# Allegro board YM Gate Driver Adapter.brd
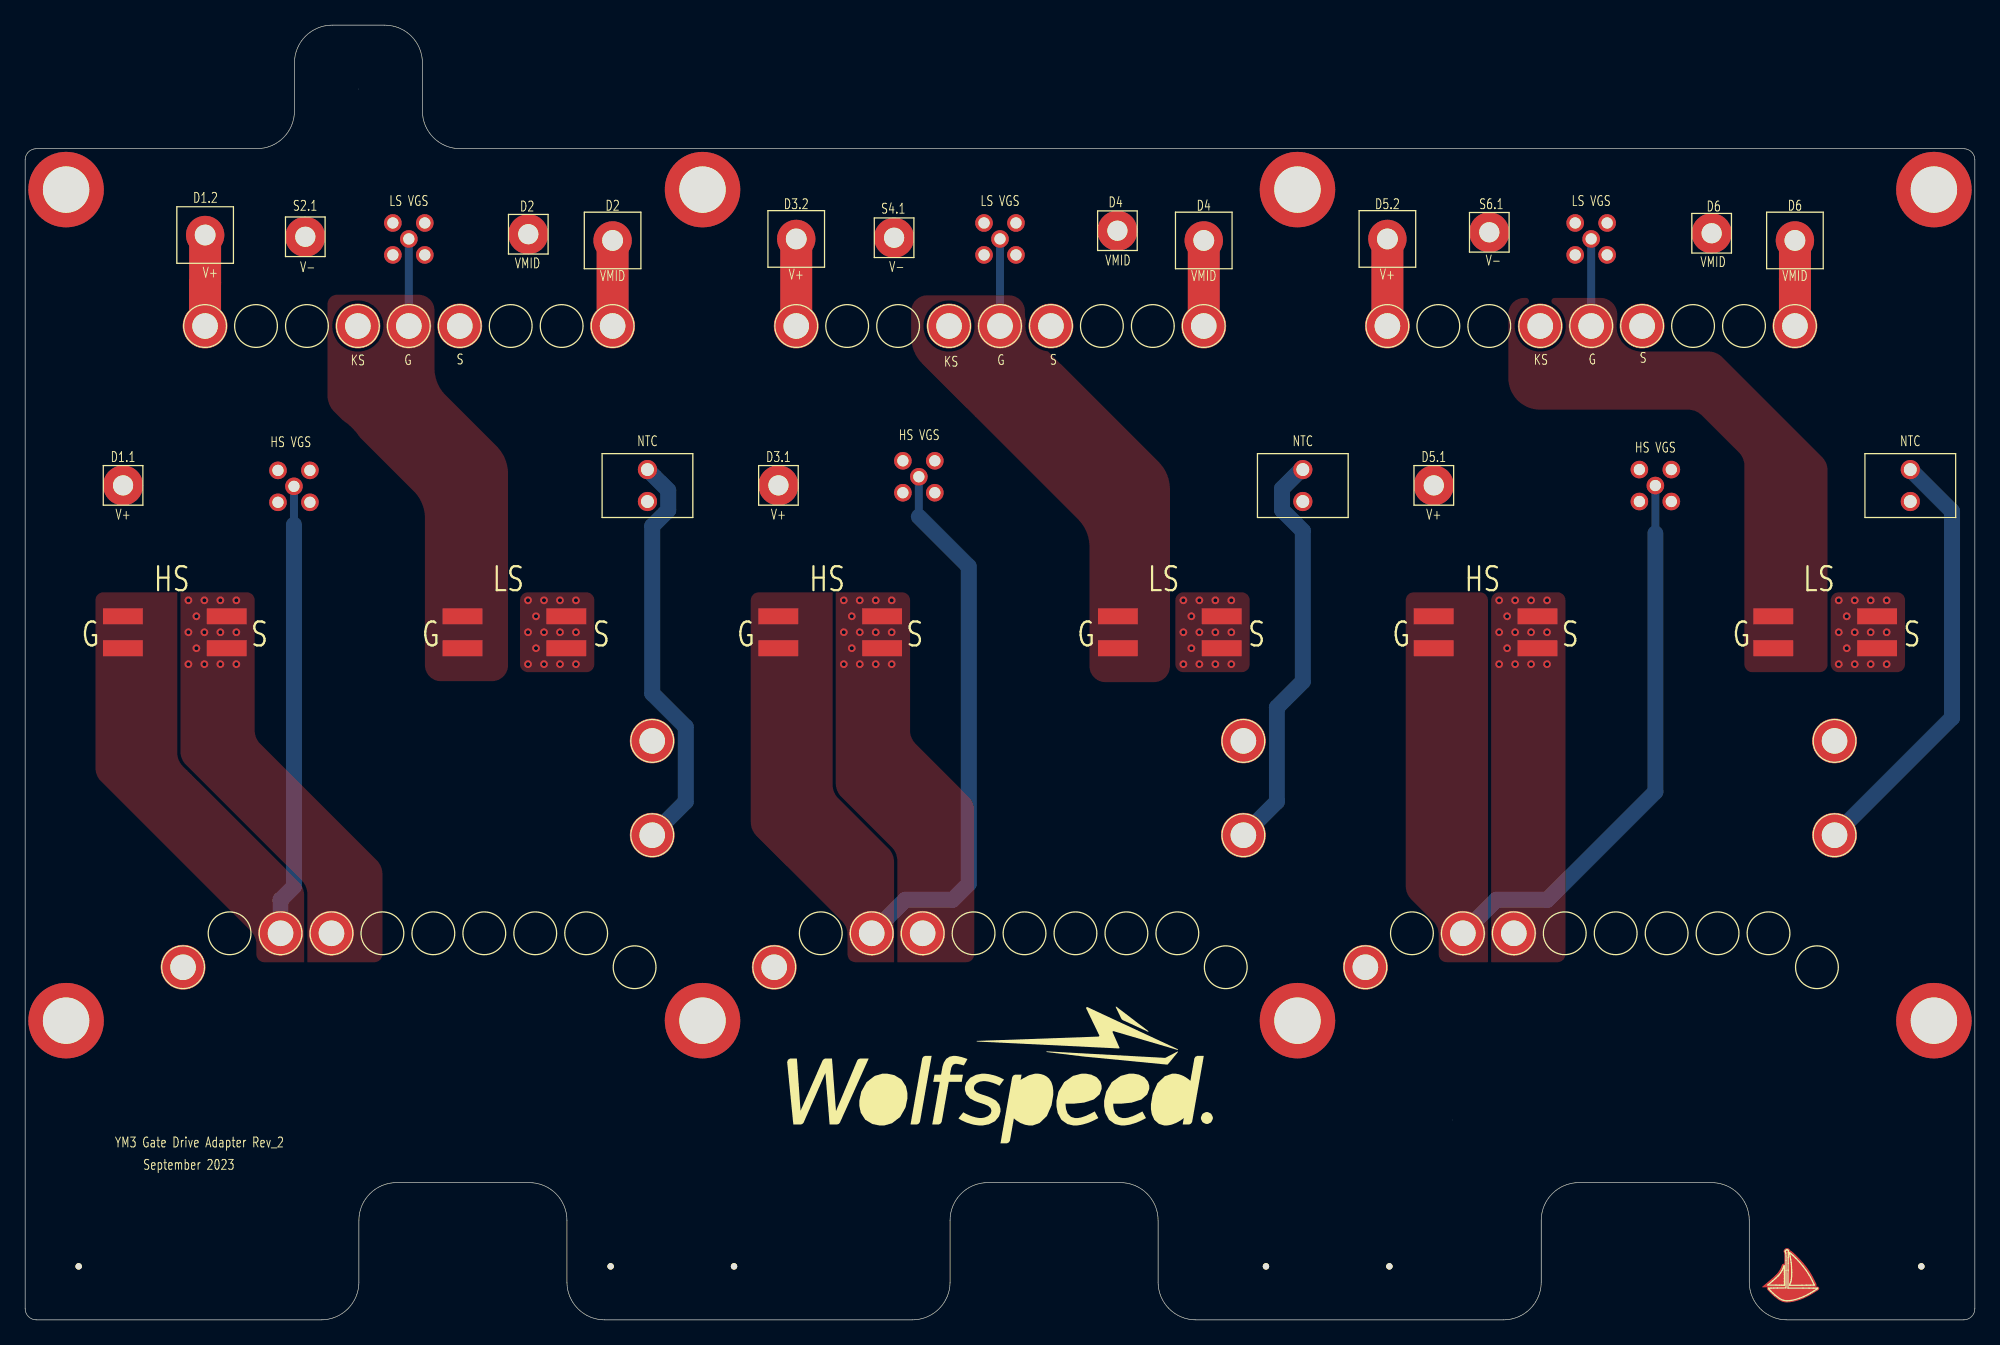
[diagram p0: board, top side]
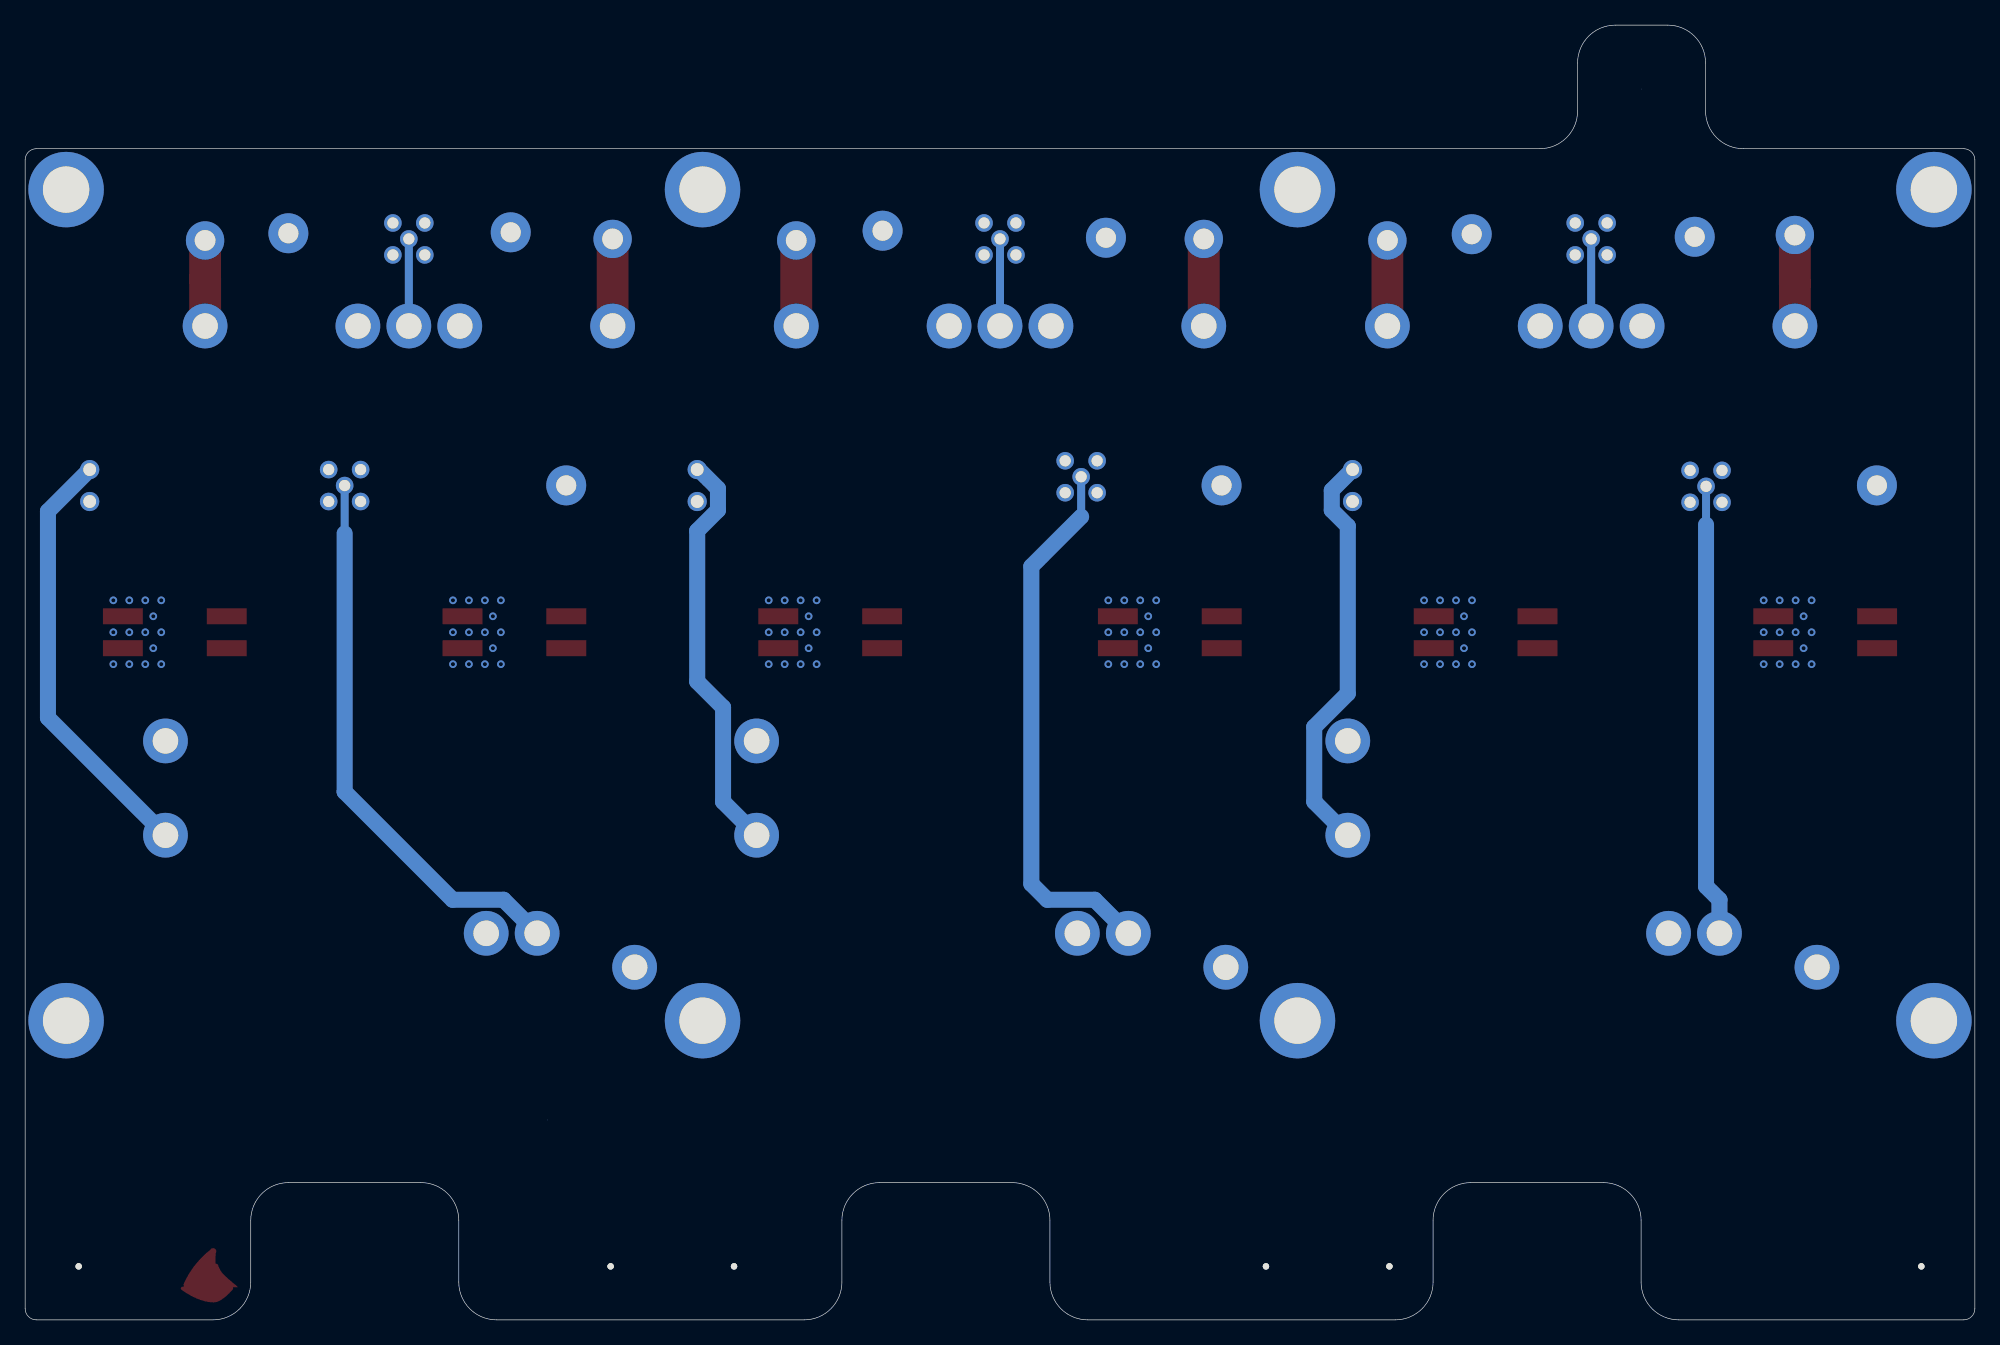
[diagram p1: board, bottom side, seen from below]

Outline 155.01 x 102.98 mm; copper layers: TOP, LAYER2, LAYER3, BOTTOM. Coordinates in mm from the lower left corner of the outline.
Outline path: 0,92.26 arc(0.26,92.89) 0.89,93.15 18.41,93.15 arc(20.53,94.03) 21.41,96.15 21.41,99.98 arc(22.29,102.1) 24.41,102.98 28.58,102.98 arc(30.71,102.1) 31.58,99.98 31.58,96.15 arc(32.46,94.03) 34.58,93.15 154.12,93.15 arc(154.75,92.89) 155.01,92.26 155.01,0.89 arc(154.75,0.26) 154.12,0 140.07,0 arc(137.95,0.88) 137.07,3 137.07,7.92 arc(136.2,10.04) 134.07,10.92 123.53,10.92 arc(121.41,10.04) 120.53,7.92 120.53,3 arc(119.66,0.88) 117.53,0 93.07,0 arc(90.95,0.88) 90.07,3 90.07,7.92 arc(89.2,10.04) 87.07,10.92 76.53,10.92 arc(74.41,10.04) 73.53,7.92 73.53,3 arc(72.66,0.88) 70.53,0 46.07,0 arc(43.95,0.88) 43.07,3 43.07,7.92 arc(42.2,10.04) 40.07,10.92 29.53,10.92 arc(27.41,10.04) 26.53,7.92 26.53,3 arc(25.66,0.88) 23.53,0 0.89,0 arc(0.26,0.26) 0,0.89 0,92.26

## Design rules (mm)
constraint set DEFAULT: min track width 0.254
net group NTC1: nets T1.1 T1.2
net group NTC2: nets T2.1 T2.2
net group NTC3: nets T3.1 T3.2
net group V+_1: nets D1.1 D1.2
net group V+_2: nets D3.1 D3.2
net group V+_3: nets D5.1 D5.2
net group V-_1: nets S2.2
net group V-_2: nets S4.2
net group V-_3: nets S6.2
net group VMID_1: nets D2
net group VMID_2: nets D4
net group VMID_3: nets D6

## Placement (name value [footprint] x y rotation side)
JT1  735187-2  [CON_1X1_63MIL]  14.31 86.28 0 top
JT2  TEST POINT  [CON1_TP]  22.27 86.14 0 top
JT3  DNP  [MMCX_PLUG_TH]  30.5 85.97 0 top
JT4  735187-2  [CON_1X1_63MIL]  61.3 85.97 0 top
JT5  TEST POINT  [CON1_TP]  69.08 86.07 0 top
JT6  DNP  [MMCX_PLUG_TH]  77.5 85.97 0 top
JT7  735187-2  [CON_1X1_63MIL]  108.3 85.97 0 top
JT8  TEST POINT  [CON1_TP]  116.4 86.5 0 top
JT9  DNP  [MMCX_PLUG_TH]  124.5 85.97 0 top
JT10  TEST POINT  [CON1_TP]  40 86.35 0 top
JT11  735187-2  [CON_1X1_63MIL]  46.7 85.85 0 top
JT12  TEST POINT  [CON1_TP]  86.84 86.63 0 top
JT13  735187-2  [CON_1X1_63MIL]  93.7 85.85 0 top
JT14  TEST POINT  [CON1_TP]  134.08 86.42 0 top
JT15  735187-2  [CON_1X1_63MIL]  140.7 85.85 0 top
JT16  TEST POINT  [CON1_TP]  7.79 66.37 0 top
JT17  DNP  [MMCX_PLUG_TH]  21.37 66.29 0 top
JT18  0022280020  [CONN_HEADER_2POS_LOCKING]  49.48 66.36 0 top
JT19  TEST POINT  [CON1_TP]  59.89 66.37 0 top
JT20  DNP  [MMCX_PLUG_TH]  71.05 67.06 0 top
JT21  0022280020  [CONN_HEADER_2POS_LOCKING]  101.58 66.36 0 top
JT22  TEST POINT  [CON1_TP]  111.99 66.37 0 top
JT23  DNP  [MMCX_PLUG_TH]  129.61 66.36 0 top
JT24  0022280020  [CONN_HEADER_2POS_LOCKING]  149.88 66.36 0 top
NOREF  -  []  77.5 19.48 0 top
NOREF#2  -  []  138.32 1.33 0 top
NOREF#3  -  []  0 46.57 0 top
NOREF#4  -  []  138.32 1.33 0 top
NOREF#5  -  []  58.3 0 90 top
UT1  HybridPack_DriverOnly  [HYBRIDPACK_DRIVERONLY]  26.5 97.9 0 top
UT2  XGD1700HB2P-FM3  [XGD1700HB2P-FM3_NOMIDDLEMOUNT]  25.4 29.84 180 top
UT3  XGD1700HB2P-FM3  [XGD1700HB2P-FM3_NOMIDDLEMOUNT]  77.5 29.84 180 top
UT4  XGD1700HB2P-FM3  [XGD1700HB2P-FM3_NOMIDDLEMOUNT]  129.61 29.84 180 top

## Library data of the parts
JT1 JT4 JT7 JT11 JT13 JT15 = HDR_1X1_M
JT2 JT5 JT8 JT10 JT12 JT14 JT16 JT19 JT22 = TEST POINT
JT3 JT6 JT9 JT17 JT20 JT23 = BNC_5P
JT18 JT21 JT24 = 0022280020
UT1 = HybridPack_DriverOnly_2
UT2-UT4 = XGD1700HB2P-FM3

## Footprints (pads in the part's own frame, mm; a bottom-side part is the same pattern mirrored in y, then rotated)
CON1_TP
  round 3.175 hole 1.6: 1(0,0)
CON_1X1_63MIL
  round 3.048 hole 1.651: 1(0,0)
CONN_HEADER_2POS_LOCKING
  round 1.524 hole 1.016: 1(0,1.27) 2(0,-1.27)
HYBRIDPACK_DRIVERONLY
  round 6 hole 3.683: (-23.25,-8) (-23.25,-74.1) (27.35,-74.1) (27.351,-8.001) (74.65,-8) (74.65,-74.1) (125.25,-8) (125.25,-74.1)
  round 0.025 hole 5.842 unplated: (0,0)
  round 0.025 hole 4.826 unplated: (87,-82)
  round 3.556 hole 2.032: 1(-12.2,-18.85) 2(-13.95,-69.85) 3(-6.2,-67.15) 4(-2.15,-67.15) 5(20.2,-18.85) 6(4,-18.85) 7(-0.05,-18.85) 8(8.05,-18.85) 9(34.8,-18.85) 10(33.05,-69.85) 11(40.8,-67.15) 12(44.85,-67.15) 13(67.2,-18.85) 14(51,-18.85) 15(46.95,-18.85) 16(55.05,-18.85) 17(81.8,-18.85) 18(80.05,-69.85) 19(87.8,-67.15) 20(91.85,-67.15) 21(114.2,-18.85) 22(98,-18.85) 23(93.95,-18.85) 24(102.05,-18.85) 25(23.35,-51.85) 26(23.35,-59.35) 27(70.35,-51.85) 28(70.35,-59.35) 29(117.35,-51.85) 30(117.35,-59.35)
MMCX_PLUG_TH
  round 1.397 hole 0.889: 1(0,0) 2(-1.27,1.27) 3(1.27,1.27) 4(1.27,-1.27) 5(-1.27,-1.27)
XGD1700HB2P-FM3_NOMIDDLEMOUNT
  round 0.508 hole 4.445 unplated: (-21.146,25.591) (21.146,25.591)
  rect 3.175x1.27 smd: 1(17.628,-26.115) 2(9.373,-26.115) 3(-9.373,-26.115) 4(-17.628,-26.115) 12(17.628,-23.575) 22(9.373,-23.575) 32(-9.373,-23.575) 42(-17.628,-23.575)

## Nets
D1.1: JT16.1 UT1.2
D1.2: JT1.1 UT1.1
D2: JT10.1 JT11.1 UT1.5
D3.1: JT19.1 UT1.10
D3.2: JT4.1 UT1.9
D4: JT12.1 JT13.1 UT1.13
D5.1: JT22.1 UT1.18
D5.2: JT7.1 UT1.17
D6: JT14.1 JT15.1 UT1.21
G1: JT17.1(SIGNAL) UT1.3 UT2.1 UT2.12
G2: JT3.1(SIGNAL) UT1.6 UT2.3 UT2.32
G3: JT20.1(SIGNAL) UT1.11 UT3.1 UT3.12
G4: JT6.1(SIGNAL) UT1.14 UT3.3 UT3.32
G5: JT23.1(SIGNAL) UT1.19 UT4.1 UT4.12
G6: JT9.1(SIGNAL) UT1.22 UT4.3 UT4.32
S1: JT17.2 JT17.3 JT17.4 JT17.5 UT1.4 UT2.2 UT2.22
S2.1: JT2.1 JT3.2 JT3.3 JT3.4 JT3.5 UT1.7 UT2.4 UT2.42(LS-SOURCE-2)
S2.2: UT1.8
S3: JT20.2 JT20.3 JT20.4 JT20.5 UT1.12 UT3.2 UT3.22
S4.1: JT5.1 JT6.2 JT6.3 JT6.4 JT6.5 UT1.15 UT3.4 UT3.42(LS-SOURCE-2)
S4.2: UT1.16
S5: JT23.2 JT23.3 JT23.4 JT23.5 UT1.20 UT4.2 UT4.22
S6.1: JT8.1 JT9.2 JT9.3 JT9.4 JT9.5 UT1.23 UT4.4 UT4.42(LS-SOURCE-2)
S6.2: UT1.24
T1.1: JT18.2 UT1.25
T1.2: JT18.1 UT1.26
T2.1: JT21.2 UT1.27
T2.2: JT21.1 UT1.28
T3.1: JT24.2 UT1.29
T3.2: JT24.1 UT1.30(T3.2)

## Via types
v1: diameter 0.61, hole 0.33, TOP to BOTTOM, 84 vias

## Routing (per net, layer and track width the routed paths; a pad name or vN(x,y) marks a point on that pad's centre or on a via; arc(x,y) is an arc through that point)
D1.1: length 45.5
  LAYER3 w1.27: UT1.2 1.56,39.04 1.56,60.14 JT16.1
D1.2: length 7.2
  TOP w0.635: 14.3,82.47 14.31,82.48
  TOP w2.54: UT1.1 14.3,82.47 ; 14.31,82.48 JT1.1
D2: length 16.9
  TOP w2.54: UT1.5 JT11.1
  LAYER2 w2.54: UT1.5 40,85.75 JT10.1
D3.1: length 41.9
  LAYER3 w1.27: UT1.10 55.41,32.19 55.41,61.89 JT19.1
D3.2: length 6.9
  TOP w2.54: UT1.9 JT4.1
D4: length 17.2
  TOP w2.54: UT1.13 JT13.1
  LAYER2 w2.54: JT12.1 86.84,85.91 UT1.13
D5.1: length 40.6
  LAYER3 w1.27: UT1.18 106.55,60.93 JT22.1
D5.2: length 6.9
  TOP w2.54: UT1.17 JT7.1
D6: length 16.9
  TOP w2.54: JT15.1 140.7,82.8 UT1.21
  LAYER2 w2.54: UT1.21 134.08,85.67 JT14.1
G1: length 36
  BOTTOM w0.635: JT17.1 21.37,63.25
  BOTTOM w1.27: 21.37,63.25 21.37,34.48 20.3,33.41 UT1.3
G2: length 6.9
  BOTTOM w0.635: JT3.1 UT1.6
G3: length 43.4
  BOTTOM w0.635: JT20.1 71.05,63.88
  BOTTOM w1.27: 71.05,63.88 75.01,59.92 75.01,34.68 73.74,33.41 69.97,33.41 UT1.11
G4: length 6.9
  BOTTOM w0.635: JT6.1 77.5,84.17 UT1.14
G5: length 44.3
  BOTTOM w0.635: 129.61,62.55 JT23.1
  BOTTOM w1.27: 129.61,62.55 129.61,42 121.02,33.41 116.97,33.41 UT1.19
G6: length 6.9
  BOTTOM w0.635: UT1.22 JT9.1
S1: length 33.2
  LAYER3 w2.54: 21.37,62.74 21.37,37.03 24.35,34.05 UT1.4
  vias: v1(12.98,57.23) v1(12.98,54.69) v1(12.98,52.15) v1(13.61,55.96) v1(13.61,53.42) v1(14.25,57.23) v1(14.25,54.69) v1(14.25,52.15) v1(15.52,57.23) v1(15.52,54.69) v1(15.52,52.15) v1(16.79,57.23) v1(16.79,54.69) v1(16.79,52.15)
S2.1: length 8.8
  LAYER2 w2.54: UT1.7 22.27,83.23 JT2.1
  vias: v1(39.98,57.23) v1(39.98,54.69) v1(39.98,52.15) v1(40.61,55.96) v1(40.61,53.42) v1(41.25,57.23) v1(41.25,54.69) v1(41.25,52.15) v1(42.52,57.23) v1(42.52,54.69) v1(42.52,52.15) v1(43.79,57.23) v1(43.79,54.69) v1(43.79,52.15)
S3: length 36.4
  LAYER3 w2.54: 71.05,63.91 75.07,59.9 75.07,34.46 UT1.12
  vias: v1(65.08,57.23) v1(65.08,54.69) v1(65.08,52.15) v1(65.72,55.96) v1(65.72,53.42) v1(66.35,57.23) v1(66.35,54.69) v1(66.35,52.15) v1(67.62,57.23) v1(67.62,54.69) v1(67.62,52.15) v1(68.89,57.23) v1(68.89,54.69) v1(68.89,52.15)
S4.1: length 8.8
  LAYER2 w2.54: JT5.1 69.08,83.42 UT1.15
  vias: v1(92.08,57.23) v1(92.08,54.69) v1(92.08,52.15) v1(92.72,55.96) v1(92.72,53.42) v1(93.35,57.23) v1(93.35,54.69) v1(93.35,52.15) v1(94.62,57.23) v1(94.62,54.69) v1(94.62,52.15) v1(95.89,57.23) v1(95.89,54.69) v1(95.89,52.15)
S5: length 36.5
  LAYER3 w2.54: UT1.20 129.61,42 129.61,62.55
  vias: v1(117.19,57.23) v1(117.19,54.69) v1(117.19,52.15) v1(117.82,55.96) v1(117.82,53.42) v1(118.46,57.23) v1(118.46,54.69) v1(118.46,52.15) v1(119.73,57.23) v1(119.73,54.69) v1(119.73,52.15) v1(121,57.23) v1(121,54.69) v1(121,52.15)
S6.1: length 9.1
  LAYER2 w2.54: JT8.1 116.4,83.1 UT1.23
  vias: v1(144.19,57.23) v1(144.19,54.69) v1(144.19,52.15) v1(144.82,55.96) v1(144.82,53.42) v1(145.46,57.23) v1(145.46,54.69) v1(145.46,52.15) v1(146.73,57.23) v1(146.73,54.69) v1(146.73,52.15) v1(148,57.23) v1(148,54.69) v1(148,52.15)
T1.1: length 19.2
  LAYER3 w1.27: UT1.25 49.85,64.71 JT18.2
T1.2: length 32.5
  BOTTOM w1.27: JT18.1 51.13,65.98 51.13,64.4 49.85,63.13 49.85,49.82 52.52,47.15 52.52,41.21 UT1.26
T2.1: length 21
  LAYER3 w1.27: JT21.2 101.58,50.77 UT1.27
T2.2: length 32.5
  BOTTOM w1.27: JT21.1 101.44,67.63 99.93,66.11 99.93,64.4 101.58,62.75 101.58,50.77 99.52,48.71 99.52,41.21 UT1.28
T3.1: length 28.7
  LAYER3 w1.27: UT1.29 151.35,46.05 153.2,47.89 153.2,61.77 JT24.2
T3.2: length 34.3
  BOTTOM w1.27: JT24.1 153.2,64.31 153.2,47.89 UT1.30

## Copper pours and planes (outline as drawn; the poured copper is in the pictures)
G1 on TOP: 22.18,28.45 22.18,33.75 22.07,34.34 21.73,34.84 12.54,44.03 12.21,44.53 12.09,45.12 12.09,57.87 6.22,57.87 5.77,57.68 5.59,57.23 5.59,43.91 5.7,43.32 6.04,42.83 17.93,30.93 18.27,30.43 18.38,29.84 18.38,29.08 18.57,28.63 19.02,28.45
G3 on TOP: 69.08,28.45 69.08,36.42 68.97,37 68.63,37.5 64.64,41.49 64.31,41.99 64.19,42.57 64.19,57.87 58.33,57.87 57.88,57.68 57.69,57.23 57.69,39.58 57.81,39 58.14,38.5 64.93,31.71 65.27,31.21 65.38,30.62 65.38,29.08 65.57,28.63 66.02,28.45
G4 on TOP: 70.44,80.21 70.81,81.11 71.71,81.48 78.22,81.48 79.11,81.11 79.49,80.21 79.49,80.13 79.72,78.96 80.38,77.96 90.12,68.23 90.78,67.24 91.01,66.06 91.01,51.99 90.64,51.1 89.74,50.72 85.89,50.72 84.99,51.1 84.62,51.99 84.62,61.49 84.38,62.67 83.72,63.66 71.34,76.04 70.68,77.03 70.44,78.21
G6 on TOP: 117.92,80.01 118.29,80.91 119.19,81.28 125.25,81.28 126.19,80.89 126.58,79.95 126.58,79.55 127.32,77.76 129.12,77.01 133.84,77.01 134.43,76.9 134.92,76.56 142.85,68.64 143.18,68.14 143.3,67.55 143.3,52.15 143.11,51.7 142.66,51.52 137.32,51.52 136.87,51.7 136.69,52.15 136.69,67.92 136.57,68.51 136.24,69 133.3,71.94 132.8,72.27 132.22,72.39 120.46,72.39 118.66,73.13 117.92,74.93
S1 on TOP: 12.34,57.87 17.61,57.87 18.06,57.68 18.25,57.23 18.25,46.89 18.37,46.3 18.7,45.8 27.95,36.55 28.29,36.05 28.4,35.46 28.4,29.08 28.22,28.63 27.77,28.45 22.44,28.45 22.44,33.86 22.32,34.44 21.99,34.94 12.79,44.14 12.46,44.63 12.34,45.22
S1 on LAYER2: 27.77,28.45 28.22,28.63 28.4,29.08 28.4,35.46 28.29,36.05 27.95,36.55 18.7,45.8 18.37,46.3 18.25,46.89 18.25,57.23 18.06,57.68 17.61,57.87 6.22,57.87 5.77,57.68 5.59,57.23 5.59,43.91 5.7,43.32 6.04,42.83 18.13,30.73 22.34,30.73 22.34,28.45
S1 on LAYER3: 17.56,66.29 25.18,66.29
S2.1 on TOP: 44.62,51.52 45.06,51.7 45.25,52.15 45.25,57.23 45.06,57.68 44.62,57.87 39.98,57.87 39.53,57.68 39.34,57.23 39.34,52.15 39.53,51.7 39.98,51.52
S2.1 on LAYER2: 24.04,80.77 24.26,81.31 24.8,81.53 31.78,81.53 32.32,81.31 32.55,80.77 32.55,75.69 32.78,74.52 33.44,73.52 45.36,61.6 46.03,60.61 46.26,59.44 46.26,52.07 45.89,51.17 44.99,50.8 33.05,50.8 32.16,51.17 31.78,52.07 31.78,63.75 31.55,64.93 30.89,65.92 24.93,71.87 24.27,72.87 24.04,74.04
S2.1 on LAYER3: 27.21,87.63 28.03,89.61 30.01,90.42 30.51,90.42 32.49,89.61 33.31,87.63 33.31,82.55 32.94,81.65 32.04,81.28 29.75,81.28 28.85,80.91 28.48,80.01 28.48,77.47 28.11,76.57 27.21,76.2 25.18,76.2 24.28,76.57 23.91,77.47 23.91,82.55 24.28,83.45 25.18,83.82 25.94,83.82 26.84,84.19 27.21,85.09
S3 on TOP: 64.45,57.87 69.72,57.87 70.17,57.68 70.35,57.23 70.35,46.89 70.47,46.3 70.8,45.8 75.01,41.6 75.34,41.1 75.46,40.51 75.46,29.08 75.27,28.63 74.82,28.45 69.34,28.45 69.34,36.52 69.22,37.11 68.89,37.6 64.9,41.59 64.57,42.09 64.45,42.68
S3 on LAYER2: 74.82,28.45 75.27,28.63 75.46,29.08 75.46,40.51 75.34,41.1 75.01,41.6 70.8,45.8 70.47,46.3 70.35,46.89 70.35,57.23 70.17,57.68 69.72,57.87 58.33,57.87 57.88,57.68 57.69,57.23 57.69,39.58 57.81,39 58.14,38.5 64.93,31.71 65.27,31.21 65.38,30.62 65.51,30.75 69.34,30.75 69.34,28.45
S3 on LAYER3: 67.24,67.06 74.86,67.06
S4.1 on TOP: 96.72,51.52 97.17,51.7 97.35,52.15 97.35,57.23 97.17,57.68 96.72,57.87 92.08,57.87 91.63,57.68 91.45,57.23 91.45,52.15 91.63,51.7 92.08,51.52
S4.1 on LAYER2: 70.42,80.21 70.79,81.11 71.69,81.48 78.29,81.48 79.19,81.11 79.56,80.21 79.56,79.53 79.7,78.82 80.1,78.23 97,61.32 97.67,60.33 97.9,59.16 97.9,51.99 97.53,51.1 96.63,50.72 85.89,50.72 84.99,51.1 84.62,51.99 84.62,61.47 84.38,62.64 83.72,63.64 71.32,76.04 70.65,77.03 70.42,78.21
S4.1 on LAYER3: 74.35,88.01 75.17,89.99 77.15,90.81 77.66,90.81 79.63,89.99 80.45,88.01 80.45,82.93 80.08,82.03 79.18,81.66 76.89,81.66 76,81.29 75.62,80.39 75.62,77.85 75.25,76.95 74.35,76.58 72.32,76.58 71.42,76.95 71.05,77.85 71.05,82.93 71.42,83.83 72.32,84.2 73.08,84.2 73.98,84.57 74.35,85.47
S5 on LAYER2: 121.82,28.45 122.27,28.63 122.46,29.08 122.46,57.23 122.27,57.68 121.82,57.87 110.4,57.87 109.95,57.68 109.76,57.23 109.76,34.51 109.88,33.93 110.21,33.43 111.93,31.71 112.27,31.21 112.38,30.62 112.51,30.75 116.3,30.75 116.3,28.45
S5 on LAYER3: 125.8,66.36 133.42,66.36
S6.1 on TOP: 148.82,51.52 149.27,51.7 149.46,52.15 149.46,57.23 149.27,57.68 148.82,57.87 144.19,57.87 143.74,57.68 143.55,57.23 143.55,52.15 143.74,51.7 144.19,51.52
S6.1 on LAYER2: 117.92,80.01 118.29,80.91 119.19,81.28 125.31,81.28 126.2,80.91 126.58,80.01 126.58,79.68 127.32,77.88 129.12,77.14 133.08,77.14 134.25,76.91 135.25,76.24 149.01,62.48 149.34,61.98 149.46,61.39 149.46,52.15 149.27,51.7 148.82,51.52 137.32,51.52 136.87,51.7 136.69,52.15 136.69,67.94 136.57,68.53 136.24,69.03 133.32,71.94 132.83,72.27 132.24,72.39 120.46,72.39 118.66,73.13 117.92,74.93
S6.1 on LAYER3: 121.34,88.27 122.16,90.24 124.14,91.06 124.65,91.06 126.62,90.24 127.44,88.27 127.44,83.19 127.07,82.29 126.17,81.91 123.88,81.91 122.99,81.54 122.61,80.64 122.61,78.1 122.24,77.21 121.34,76.83 119.31,76.83 118.41,77.21 118.04,78.1 118.04,83.19 118.41,84.08 119.31,84.45 120.07,84.45 120.97,84.83 121.34,85.72

Small or netless copper shapes (teardrops, artwork), in the pictures only: 4 on TOP

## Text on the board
Ref Des/Silkscreen Top: D1.1 | V+ | September 2023 | YM3 Gate Drive Adapter Rev_2 | D1.2 | HS VGS | S2.1 | V- | KS | G | LS VGS | S | D2 | VMID | NTC | D3.1 | D3.2 | S4.1 | D4 | D5.2 | D5.1 | S6.1 | D6
NCLEGEND-1-4: FIGURE | FINISHED_SIZE | 13.0 | 35.0 | 40.0 | 63.0 | 65.0 | 80.0 | 145.0 | 175.0 | 190.0 | 230.0 | DRILL CHART: TOP to BOTTOM | ALL UNITS ARE IN MILS | PLATED | NON-PLATED | QTY | 84 | 30 | 6 | 9 | 8 | 1 | 181 | TOTAL HOLES:
